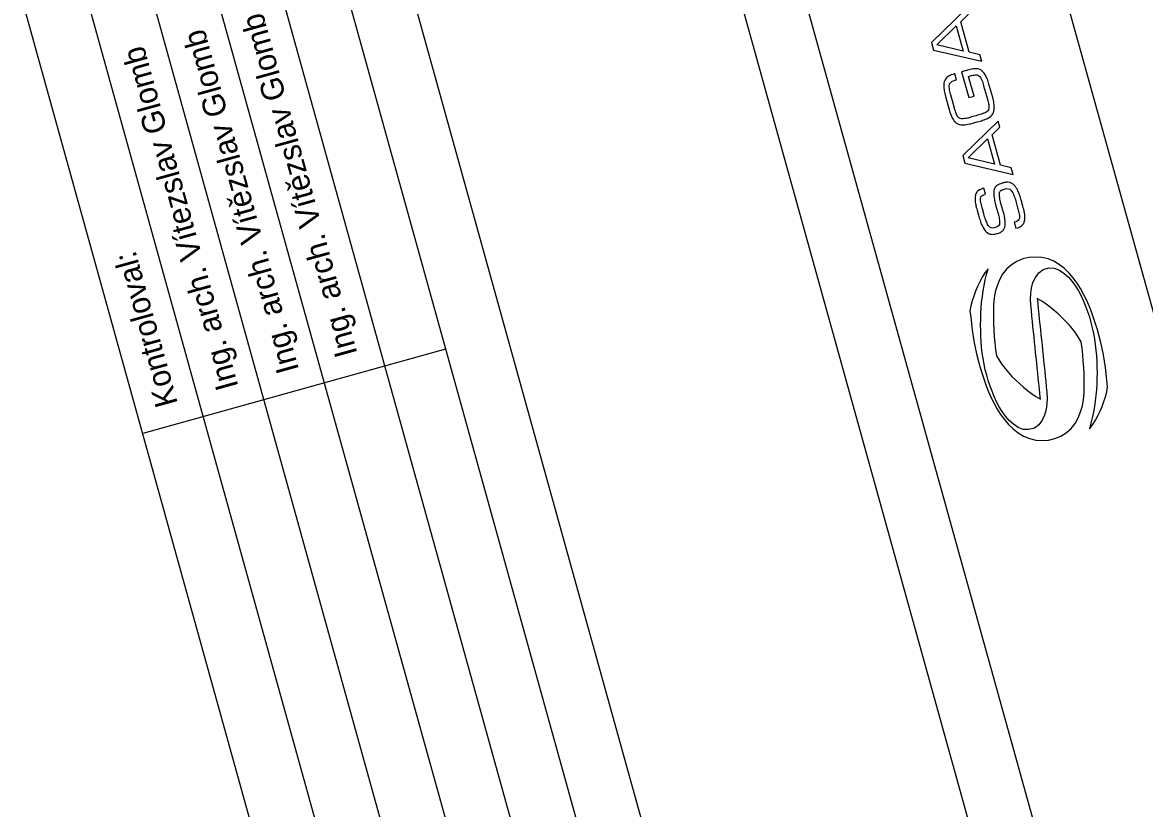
# Model space of a CAD drawing. Extents: x -821122 to -820555, y -1070892 to -1069801.
# Drawn here: x -821033.4 to -820944.2, y -1069943.1 to -1069880.6 of the extents above; entities that cross this region are included whole.
import ezdxf

# ---------------------------------------------------------------- set-up
doc = ezdxf.new("R2010")
doc.units = 0
doc.layers.add('Popisove_pole', color=7, linetype='Continuous')

# ---------------------------------------------------------------- blocks, each defined once
blk = doc.blocks.new('sagasta-logo')
at = {"layer": 'Popisove_pole'}
for p, q in [((-0.4043, 0.0893), (-0.414, 0.0863)), ((-0.3943, 0.0916), (-0.4043, 0.0893)), ((-0.3843, 0.0934), (-0.3943, 0.0916)), ((-0.3742, 0.0949), (-0.3843, 0.0934)), ((-0.3838, 0.0884), (-0.3749, 0.0895)), ((-0.3749, 0.0895), (-0.3659, 0.0903)), ((-0.3641, 0.096), (-0.3742, 0.0949)), ((-0.3659, 0.0903), (-0.3569, 0.0907)), ((-0.3539, 0.0968), (-0.3641, 0.096)), ((-0.3569, 0.0907), (-0.3479, 0.0908)), ((-0.3437, 0.0972), (-0.3539, 0.0968)), ((-0.3479, 0.0908), (-0.3389, 0.0906)), ((-0.3335, 0.0975), (-0.3437, 0.0972)), ((-0.3389, 0.0906), (-0.33, 0.0901)), ((-0.3233, 0.0976), (-0.3335, 0.0975)), ((-0.33, 0.0901), (-0.321, 0.0892)), ((-0.3131, 0.0975), (-0.3233, 0.0976)), ((-0.303, 0.097), (-0.3131, 0.0975)), ((-0.2928, 0.0962), (-0.303, 0.097)), ((-0.2827, 0.0951), (-0.2928, 0.0962)), ((-0.2726, 0.0938), (-0.2827, 0.0951)), ((-0.2625, 0.0922), (-0.2726, 0.0938)), ((-0.2524, 0.0907), (-0.2625, 0.0922)), ((-0.2423, 0.0891), (-0.2524, 0.0907)), ((-0.4415, 0.0731), (-0.4497, 0.067)), ((-0.4328, 0.0783), (-0.4415, 0.0731)), ((-0.4343, 0.0708), (-0.4267, 0.0757)), ((-0.4235, 0.0826), (-0.4328, 0.0783)), ((-0.4267, 0.0757), (-0.4186, 0.0794)), ((-0.414, 0.0863), (-0.4235, 0.0826)), ((-0.4186, 0.0794), (-0.4101, 0.0825)), ((-0.4101, 0.0825), (-0.4015, 0.085)), ((-0.4015, 0.085), (-0.3927, 0.0869)), ((-0.3927, 0.0869), (-0.3838, 0.0884)), ((-0.321, 0.0892), (-0.3121, 0.0881)), ((-0.3121, 0.0881), (-0.3032, 0.0867)), ((-0.3032, 0.0867), (-0.2944, 0.085)), ((-0.2944, 0.085), (-0.2855, 0.0832)), ((-0.2855, 0.0832), (-0.2768, 0.081)), ((-0.2768, 0.081), (-0.2681, 0.0787)), ((-0.2681, 0.0787), (-0.2595, 0.0762)), ((-0.2595, 0.0762), (-0.2509, 0.0735)), ((-0.2509, 0.0735), (-0.2424, 0.0706)), ((-0.235, 0.0855), (-0.2423, 0.0891)), ((-0.228, 0.0814), (-0.235, 0.0855)), ((-0.2211, 0.077), (-0.228, 0.0814)), ((-0.2145, 0.0722), (-0.2211, 0.077)), ((-0.2081, 0.0671), (-0.2145, 0.0722)), ((-0.4572, 0.0602), (-0.4634, 0.0521)), ((-0.4497, 0.067), (-0.4572, 0.0602)), ((-0.4493, 0.0493), (-0.4465, 0.0578)), ((-0.4465, 0.0578), (-0.4412, 0.065)), ((-0.4412, 0.065), (-0.4343, 0.0708)), ((-0.3532, 0.0564), (-0.3606, 0.0526)), ((-0.3457, 0.0599), (-0.3532, 0.0564)), ((-0.338, 0.0629), (-0.3457, 0.0599)), ((-0.3302, 0.0655), (-0.338, 0.0629)), ((-0.3222, 0.0677), (-0.3302, 0.0655)), ((-0.3121, 0.0662), (-0.3222, 0.0677)), ((-0.302, 0.0646), (-0.3121, 0.0662)), ((-0.292, 0.0627), (-0.302, 0.0646)), ((-0.282, 0.0606), (-0.292, 0.0627)), ((-0.2721, 0.0584), (-0.282, 0.0606)), ((-0.2622, 0.0559), (-0.2721, 0.0584)), ((-0.2523, 0.0533), (-0.2622, 0.0559)), ((-0.2424, 0.0706), (-0.2339, 0.0675)), ((-0.2339, 0.0675), (-0.2257, 0.0639)), ((-0.2257, 0.0639), (-0.2174, 0.0604)), ((-0.2174, 0.0604), (-0.2093, 0.0565)), ((-0.2093, 0.0565), (-0.2013, 0.0524)), ((-0.2019, 0.0617), (-0.2081, 0.0671)), ((-0.1961, 0.056), (-0.2019, 0.0617)), ((-0.1906, 0.05), (-0.1961, 0.056)), ((-0.4684, 0.0432), (-0.4717, 0.0335)), ((-0.4634, 0.0521), (-0.4684, 0.0432)), ((-0.4493, 0.0403), (-0.4493, 0.0493)), ((-0.446, 0.0319), (-0.4493, 0.0403)), ((-0.3817, 0.0396), (-0.3885, 0.0348)), ((-0.3748, 0.0442), (-0.3817, 0.0396)), ((-0.3678, 0.0485), (-0.3748, 0.0442)), ((-0.3606, 0.0526), (-0.3678, 0.0485)), ((-0.2426, 0.0503), (-0.2523, 0.0533)), ((-0.2331, 0.0466), (-0.2426, 0.0503)), ((-0.2239, 0.0422), (-0.2331, 0.0466)), ((-0.2152, 0.0369), (-0.2239, 0.0422)), ((-0.2072, 0.0306), (-0.2152, 0.0369)), ((-0.2013, 0.0524), (-0.1935, 0.048)), ((-0.1935, 0.048), (-0.1857, 0.0434)), ((-0.1857, 0.0434), (-0.1906, 0.05)), ((-0.4736, 0.0235), (-0.4741, 0.0133)), ((-0.4717, 0.0335), (-0.4736, 0.0235)), ((-0.4404, 0.0248), (-0.446, 0.0319)), ((-0.4336, 0.019), (-0.4404, 0.0248)), ((-0.4258, 0.0144), (-0.4336, 0.019)), ((-0.4014, 0.0244), (-0.4073, 0.0186)), ((-0.4073, 0.0186), (-0.3991, 0.0172)), ((-0.3951, 0.0298), (-0.4014, 0.0244)), ((-0.3885, 0.0348), (-0.3951, 0.0298)), ((-0.1999, 0.0234), (-0.2072, 0.0306)), ((-0.1939, 0.0152), (-0.1999, 0.0234)), ((-0.4741, 0.0133), (-0.4727, 0.0032)), ((-0.4727, 0.0032), (-0.4699, -0.0066)), ((-0.4176, 0.0108), (-0.4258, 0.0144)), ((-0.409, 0.0082), (-0.4176, 0.0108)), ((-0.4002, 0.0063), (-0.409, 0.0082)), ((-0.3913, 0.0046), (-0.4002, 0.0063)), ((-0.3991, 0.0172), (-0.391, 0.0158)), ((-0.3825, 0.003), (-0.3913, 0.0046)), ((-0.391, 0.0158), (-0.3828, 0.0144)), ((-0.3828, 0.0144), (-0.3747, 0.0131)), ((-0.3743, 0.0016), (-0.3825, 0.003)), ((-0.3747, 0.0131), (-0.3665, 0.0117)), ((-0.3662, 0.0002), (-0.3743, 0.0016)), ((-0.3665, 0.0117), (-0.3584, 0.0103)), ((-0.358, -0.0012), (-0.3662, 0.0002)), ((-0.3584, 0.0103), (-0.3502, 0.0089)), ((-0.3502, 0.0089), (-0.3421, 0.0075)), ((-0.3421, 0.0075), (-0.3339, 0.0062)), ((-0.3339, 0.0062), (-0.3257, 0.0048)), ((-0.3257, 0.0048), (-0.3176, 0.0034)), ((-0.3176, 0.0034), (-0.3094, 0.002)), ((-0.3094, 0.002), (-0.3013, 0.0006)), ((-0.3013, 0.0006), (-0.2931, -0.0007)), ((-0.1894, 0.0061), (-0.1939, 0.0152)), ((-0.1866, -0.0037), (-0.1894, 0.0061)), ((-0.4699, -0.0066), (-0.4654, -0.0157)), ((-0.4654, -0.0157), (-0.4594, -0.024)), ((-0.3499, -0.0025), (-0.358, -0.0012)), ((-0.3417, -0.0039), (-0.3499, -0.0025)), ((-0.3336, -0.0053), (-0.3417, -0.0039)), ((-0.3254, -0.0067), (-0.3336, -0.0053)), ((-0.3173, -0.0081), (-0.3254, -0.0067)), ((-0.3091, -0.0094), (-0.3173, -0.0081)), ((-0.301, -0.0108), (-0.3091, -0.0094)), ((-0.2928, -0.0122), (-0.301, -0.0108)), ((-0.2931, -0.0007), (-0.285, -0.0021)), ((-0.2846, -0.0136), (-0.2928, -0.0122)), ((-0.285, -0.0021), (-0.2768, -0.0035)), ((-0.2765, -0.015), (-0.2846, -0.0136)), ((-0.2768, -0.0035), (-0.268, -0.0051)), ((-0.2683, -0.0163), (-0.2765, -0.015)), ((-0.2602, -0.0177), (-0.2683, -0.0163)), ((-0.268, -0.0051), (-0.2591, -0.0068)), ((-0.252, -0.0191), (-0.2602, -0.0177)), ((-0.2591, -0.0068), (-0.2504, -0.0087)), ((-0.2504, -0.0087), (-0.2417, -0.0114)), ((-0.2417, -0.0114), (-0.2335, -0.0149)), ((-0.2335, -0.0149), (-0.2258, -0.0195)), ((-0.1852, -0.0139), (-0.1866, -0.0037)), ((-0.1857, -0.024), (-0.1852, -0.0139)), ((-0.4594, -0.024), (-0.4521, -0.0311)), ((-0.4521, -0.0311), (-0.4441, -0.0374)), ((-0.2776, -0.0401), (-0.2708, -0.0354)), ((-0.2708, -0.0354), (-0.2642, -0.0304)), ((-0.2642, -0.0304), (-0.258, -0.025)), ((-0.258, -0.025), (-0.252, -0.0191)), ((-0.2258, -0.0195), (-0.2189, -0.0253)), ((-0.2189, -0.0253), (-0.2134, -0.0324)), ((-0.2134, -0.0324), (-0.21, -0.0408)), ((-0.1909, -0.0437), (-0.1876, -0.034)), ((-0.1876, -0.034), (-0.1857, -0.024)), ((-0.4659, -0.0485), (-0.4736, -0.0439)), ((-0.4736, -0.0439), (-0.4687, -0.0505)), ((-0.4687, -0.0505), (-0.4632, -0.0565)), ((-0.458, -0.0529), (-0.4659, -0.0485)), ((-0.45, -0.057), (-0.458, -0.0529)), ((-0.4441, -0.0374), (-0.4354, -0.0428)), ((-0.4354, -0.0428), (-0.4262, -0.0471)), ((-0.4262, -0.0471), (-0.4167, -0.0508)), ((-0.4167, -0.0508), (-0.407, -0.0538)), ((-0.3061, -0.0569), (-0.2987, -0.0531)), ((-0.2987, -0.0531), (-0.2915, -0.049)), ((-0.2915, -0.049), (-0.2845, -0.0447)), ((-0.2845, -0.0447), (-0.2776, -0.0401)), ((-0.21, -0.0498), (-0.2128, -0.0583)), ((-0.21, -0.0408), (-0.21, -0.0498)), ((-0.2021, -0.0607), (-0.1959, -0.0526)), ((-0.1959, -0.0526), (-0.1909, -0.0437)), ((-0.4632, -0.0565), (-0.4574, -0.0622)), ((-0.4574, -0.0622), (-0.4512, -0.0676)), ((-0.4512, -0.0676), (-0.4449, -0.0727)), ((-0.4419, -0.0609), (-0.45, -0.057)), ((-0.4336, -0.0644), (-0.4419, -0.0609)), ((-0.4254, -0.068), (-0.4336, -0.0644)), ((-0.4169, -0.0711), (-0.4254, -0.068)), ((-0.4084, -0.074), (-0.4169, -0.0711)), ((-0.407, -0.0538), (-0.3971, -0.0564)), ((-0.3971, -0.0564), (-0.3872, -0.0589)), ((-0.3872, -0.0589), (-0.3773, -0.0611)), ((-0.3773, -0.0611), (-0.3673, -0.0632)), ((-0.3673, -0.0632), (-0.3573, -0.0651)), ((-0.3573, -0.0651), (-0.3472, -0.0667)), ((-0.3472, -0.0667), (-0.3371, -0.0682)), ((-0.3371, -0.0682), (-0.3291, -0.0661)), ((-0.3291, -0.0661), (-0.3213, -0.0635)), ((-0.3213, -0.0635), (-0.3136, -0.0604)), ((-0.3136, -0.0604), (-0.3061, -0.0569)), ((-0.225, -0.0713), (-0.2326, -0.0762)), ((-0.2181, -0.0655), (-0.225, -0.0713)), ((-0.2128, -0.0583), (-0.2181, -0.0655)), ((-0.2178, -0.0736), (-0.2096, -0.0675)), ((-0.2096, -0.0675), (-0.2021, -0.0607)), ((-0.4449, -0.0727), (-0.4382, -0.0775)), ((-0.4382, -0.0775), (-0.4314, -0.0819)), ((-0.4314, -0.0819), (-0.4243, -0.0861)), ((-0.4243, -0.0861), (-0.417, -0.0896)), ((-0.3998, -0.0767), (-0.4084, -0.074)), ((-0.3912, -0.0792), (-0.3998, -0.0767)), ((-0.3825, -0.0815), (-0.3912, -0.0792)), ((-0.3738, -0.0837), (-0.3825, -0.0815)), ((-0.365, -0.0855), (-0.3738, -0.0837)), ((-0.3561, -0.0872), (-0.365, -0.0855)), ((-0.3472, -0.0886), (-0.3561, -0.0872)), ((-0.3383, -0.0897), (-0.3472, -0.0886)), ((-0.2755, -0.0889), (-0.2844, -0.09)), ((-0.2666, -0.0874), (-0.2755, -0.0889)), ((-0.2579, -0.0855), (-0.2666, -0.0874)), ((-0.2492, -0.083), (-0.2579, -0.0855)), ((-0.2551, -0.0898), (-0.2453, -0.0868)), ((-0.2407, -0.08), (-0.2492, -0.083)), ((-0.2453, -0.0868), (-0.2358, -0.0831)), ((-0.2326, -0.0762), (-0.2407, -0.08)), ((-0.2358, -0.0831), (-0.2266, -0.0788)), ((-0.2266, -0.0788), (-0.2178, -0.0736)), ((-0.417, -0.0896), (-0.4069, -0.0912)), ((-0.4069, -0.0912), (-0.3968, -0.0928)), ((-0.3968, -0.0928), (-0.3868, -0.0943)), ((-0.3868, -0.0943), (-0.3766, -0.0956)), ((-0.3766, -0.0956), (-0.3665, -0.0967)), ((-0.3665, -0.0967), (-0.3564, -0.0976)), ((-0.3564, -0.0976), (-0.3462, -0.098)), ((-0.3462, -0.098), (-0.336, -0.0982)), ((-0.3294, -0.0906), (-0.3383, -0.0897)), ((-0.336, -0.0982), (-0.3258, -0.0981)), ((-0.3204, -0.0911), (-0.3294, -0.0906)), ((-0.3258, -0.0981), (-0.3156, -0.0978)), ((-0.3114, -0.0913), (-0.3204, -0.0911)), ((-0.3156, -0.0978), (-0.3054, -0.0973)), ((-0.3024, -0.0912), (-0.3114, -0.0913)), ((-0.3054, -0.0973), (-0.2952, -0.0966)), ((-0.2934, -0.0908), (-0.3024, -0.0912)), ((-0.2952, -0.0966), (-0.2851, -0.0955)), ((-0.2844, -0.09), (-0.2934, -0.0908)), ((-0.2851, -0.0955), (-0.275, -0.094)), ((-0.275, -0.094), (-0.265, -0.0922)), ((-0.265, -0.0922), (-0.2551, -0.0898))]:
    blk.add_line(p, q, dxfattribs=at)
for points in [[(-0.0604, -0.0144), (-0.0605, -0.0121), (-0.0607, -0.0098), (-0.0608, -0.009), (-0.0613, -0.0068), (-0.0622, -0.0048), (-0.0625, -0.0042), (-0.0637, -0.0023), (-0.0654, -0.0007), (-0.0667, 0.0003), (-0.0686, 0.0013), (-0.0709, 0.0023), (-0.0724, 0.0027), (-0.0745, 0.0032), (-0.0767, 0.0037), (-0.0792, 0.004), (-0.0796, 0.004), (-0.0816, 0.0042), (-0.0837, 0.0044), (-0.0859, 0.0045), (-0.0883, 0.0046), (-0.0908, 0.0046), (-0.102, 0.0046), (-0.1025, 0.0046), (-0.1051, 0.0046), (-0.1074, 0.0046), (-0.1095, 0.0047), (-0.1114, 0.0048), (-0.1136, 0.005), (-0.1158, 0.0052), (-0.1178, 0.0056), (-0.1201, 0.0062), (-0.1224, 0.0072), (-0.1244, 0.0091), (-0.1253, 0.0115), (-0.1254, 0.0129), (-0.1255, 0.0152), (-0.1255, 0.0165), (-0.1251, 0.0188), (-0.1243, 0.0211), (-0.1226, 0.0229), (-0.1205, 0.0241), (-0.1193, 0.0246), (-0.1174, 0.0252), (-0.1151, 0.0256), (-0.1125, 0.026), (-0.1108, 0.0262), (-0.1088, 0.0263), (-0.1067, 0.0264), (-0.1043, 0.0265), (-0.1019, 0.0266), (-0.0993, 0.0266), (-0.0911, 0.0266), (-0.0897, 0.0266), (-0.0872, 0.0266), (-0.0849, 0.0265), (-0.0829, 0.0264), (-0.081, 0.0263), (-0.0785, 0.026), (-0.0763, 0.0256), (-0.0745, 0.025), (-0.0725, 0.0237), (-0.0713, 0.022), (-0.0707, 0.0204), (-0.0704, 0.0182), (-0.0703, 0.0154), (-0.0604, 0.0154), (-0.0604, 0.0179), (-0.0606, 0.0202), (-0.0609, 0.0222), (-0.061, 0.023), (-0.0618, 0.0252), (-0.0628, 0.0271), (-0.0633, 0.0278), (-0.0647, 0.0294), (-0.0665, 0.0309), (-0.068, 0.0317), (-0.07, 0.0326), (-0.0722, 0.0334), (-0.0736, 0.0338), (-0.0757, 0.0342), (-0.0779, 0.0346), (-0.0803, 0.0349), (-0.082, 0.035), (-0.0842, 0.0352), (-0.0864, 0.0353), (-0.0887, 0.0353), (-0.0911, 0.0354), (-0.0993, 0.0354), (-0.1014, 0.0354), (-0.1038, 0.0353), (-0.1061, 0.0352), (-0.1083, 0.0351), (-0.1103, 0.035), (-0.1123, 0.0348), (-0.1134, 0.0347), (-0.1158, 0.0344), (-0.118, 0.034), (-0.1201, 0.0336), (-0.122, 0.033), (-0.1226, 0.0329), (-0.1249, 0.0321), (-0.1269, 0.0312), (-0.1286, 0.0302), (-0.1298, 0.0294), (-0.1314, 0.0278), (-0.1328, 0.0262), (-0.1333, 0.0254), (-0.1342, 0.0234), (-0.1349, 0.0212), (-0.1351, 0.0199), (-0.1354, 0.0176), (-0.1354, 0.0152), (-0.1354, 0.0141), (-0.1353, 0.0118), (-0.1351, 0.0096), (-0.135, 0.009), (-0.1344, 0.0068), (-0.1335, 0.0048), (-0.1331, 0.0041), (-0.1318, 0.0024), (-0.13, 0.0008), (-0.1283, -0.0002), (-0.1263, -0.0012), (-0.124, -0.002), (-0.1237, -0.0021), (-0.1218, -0.0026), (-0.1197, -0.003), (-0.1174, -0.0033), (-0.1149, -0.0036), (-0.1134, -0.0038), (-0.1114, -0.004), (-0.1092, -0.0041), (-0.1069, -0.0042), (-0.1045, -0.0042), (-0.102, -0.0042), (-0.0908, -0.0042), (-0.0885, -0.0042), (-0.0861, -0.0043), (-0.0838, -0.0044), (-0.0818, -0.0046), (-0.08, -0.0048), (-0.0776, -0.0053), (-0.0754, -0.0059), (-0.0737, -0.0067), (-0.072, -0.0082), (-0.0709, -0.0101), (-0.0707, -0.011), (-0.0704, -0.0131), (-0.0703, -0.0156), (-0.0703, -0.017), (-0.0706, -0.0193), (-0.0715, -0.0217), (-0.073, -0.0236), (-0.0749, -0.025), (-0.0756, -0.0253), (-0.0775, -0.026), (-0.0797, -0.0266), (-0.0822, -0.0271), (-0.0826, -0.0272), (-0.0845, -0.0274), (-0.0866, -0.0276), (-0.0888, -0.0277), (-0.0912, -0.0278), (-0.0938, -0.0278), (-0.1047, -0.0278), (-0.1063, -0.0278), (-0.1088, -0.0278), (-0.111, -0.0277), (-0.1131, -0.0276), (-0.1149, -0.0275), (-0.1172, -0.0273), (-0.1194, -0.0268), (-0.1213, -0.0262), (-0.1232, -0.0249), (-0.1245, -0.0231), (-0.125, -0.0215), (-0.1254, -0.0193), (-0.1255, -0.0165), (-0.1354, -0.0165), (-0.1353, -0.0191), (-0.1352, -0.0214), (-0.1349, -0.0233), (-0.1347, -0.0241), (-0.134, -0.0263), (-0.1329, -0.0282), (-0.1325, -0.0288), (-0.1311, -0.0305), (-0.1293, -0.032), (-0.1279, -0.0329), (-0.1258, -0.0338), (-0.1236, -0.0346), (-0.1223, -0.035), (-0.1202, -0.0354), (-0.1179, -0.0358), (-0.1155, -0.0361), (-0.1138, -0.0362), (-0.1118, -0.0364), (-0.1095, -0.0365), (-0.1072, -0.0365), (-0.1047, -0.0366), (-0.0938, -0.0366), (-0.0928, -0.0366), (-0.0904, -0.0365), (-0.0881, -0.0364), (-0.0858, -0.0363), (-0.0838, -0.0362), (-0.0818, -0.036), (-0.0792, -0.0355), (-0.077, -0.0351), (-0.0749, -0.0346), (-0.0727, -0.0339), (-0.0705, -0.0331), (-0.0685, -0.0321), (-0.0668, -0.0309), (-0.0658, -0.0301), (-0.0642, -0.0285), (-0.0629, -0.0268), (-0.0624, -0.0259), (-0.0615, -0.0238), (-0.0609, -0.0216), (-0.0607, -0.0202), (-0.0604, -0.018), (-0.0604, -0.0156), (-0.0604, -0.0144)], [(-0.0012, 0.0339), (-0.0139, 0.0339), (-0.0515, -0.0351), (-0.0406, -0.0351), (-0.0322, -0.0197), (0.0179, -0.0197), (0.0263, -0.0351), (0.0363, -0.0351), (-0.0012, 0.0339)], [(-0.0071, 0.0266), (0.0136, -0.0109), (-0.0279, -0.0109), (-0.0071, 0.0266)], [(0.0556, 0.0205), (0.0565, 0.0223), (0.0579, 0.0238), (0.0599, 0.0249), (0.0612, 0.0254), (0.0633, 0.0259), (0.0658, 0.0262), (0.0659, 0.0262), (0.0678, 0.0263), (0.07, 0.0264), (0.0723, 0.0265), (0.0748, 0.0265), (0.0967, 0.0265), (0.0981, 0.0265), (0.1005, 0.0264), (0.1028, 0.0263), (0.1049, 0.0262), (0.1067, 0.026), (0.1069, 0.026), (0.1093, 0.0256), (0.1114, 0.025), (0.1132, 0.0242), (0.114, 0.0236), (0.1155, 0.022), (0.1165, 0.0199), (0.1169, 0.0184), (0.1173, 0.0164), (0.1175, 0.0139), (0.1175, 0.0111), (0.1274, 0.0111), (0.1274, 0.0125), (0.1274, 0.0149), (0.1272, 0.0172), (0.1269, 0.0191), (0.1266, 0.0208), (0.1259, 0.023), (0.125, 0.025), (0.1243, 0.0263), (0.123, 0.028), (0.1214, 0.0296), (0.1197, 0.0308), (0.1178, 0.0319), (0.1156, 0.0328), (0.1142, 0.0333), (0.1121, 0.0338), (0.1099, 0.0343), (0.1075, 0.0346), (0.1058, 0.0349), (0.1036, 0.035), (0.1014, 0.0352), (0.0991, 0.0353), (0.0967, 0.0353), (0.0748, 0.0353), (0.0729, 0.0353), (0.0704, 0.0352), (0.0681, 0.0351), (0.066, 0.0349), (0.0639, 0.0346), (0.0621, 0.0343), (0.0617, 0.0343), (0.0593, 0.0337), (0.0572, 0.033), (0.0552, 0.0323), (0.0534, 0.0313), (0.0527, 0.0309), (0.0508, 0.0296), (0.0493, 0.028), (0.048, 0.0263), (0.0476, 0.0257), (0.0466, 0.0237), (0.0458, 0.0216), (0.0453, 0.0192), (0.0449, 0.0173), (0.0446, 0.0151), (0.0444, 0.0128), (0.0443, 0.0103), (0.0442, 0.0087), (0.0442, 0.0065), (0.0441, 0.0042), (0.0441, 0.0019), (0.0441, -0.0006), (0.0441, -0.0025), (0.0441, -0.0049), (0.0442, -0.0072), (0.0442, -0.0094), (0.0443, -0.0115), (0.0444, -0.0139), (0.0446, -0.0162), (0.0449, -0.0184), (0.0453, -0.0205), (0.0454, -0.0213), (0.0461, -0.0235), (0.0469, -0.0256), (0.048, -0.0275), (0.0484, -0.0282), (0.0498, -0.0298), (0.0514, -0.0313), (0.0537, -0.0328), (0.0554, -0.0336), (0.0574, -0.0344), (0.0596, -0.035), (0.062, -0.0355), (0.0635, -0.0358), (0.0655, -0.036), (0.0676, -0.0362), (0.0699, -0.0364), (0.0723, -0.0365), (0.0748, -0.0365), (0.0967, -0.0365), (0.0989, -0.0365), (0.1013, -0.0364), (0.1035, -0.0363), (0.1056, -0.0361), (0.1076, -0.0359), (0.1093, -0.0356), (0.1116, -0.0352), (0.1137, -0.0346), (0.1156, -0.034), (0.1178, -0.033), (0.1197, -0.0319), (0.1214, -0.0306), (0.1225, -0.0295), (0.1239, -0.0278), (0.125, -0.0258), (0.1258, -0.024), (0.1265, -0.0219), (0.1269, -0.0195), (0.127, -0.0187), (0.1273, -0.0166), (0.1274, -0.0142), (0.1274, -0.0118), (0.1274, 0.0003), (0.0849, 0.0003), (0.0849, -0.0085), (0.1175, -0.0085), (0.1175, -0.0118), (0.1175, -0.0133), (0.1174, -0.0157), (0.1172, -0.0178), (0.1169, -0.02), (0.1162, -0.022), (0.1156, -0.0231), (0.1141, -0.0248), (0.1127, -0.0257), (0.1105, -0.0265), (0.1094, -0.0268), (0.1073, -0.0272), (0.1049, -0.0274), (0.1036, -0.0275), (0.1015, -0.0276), (0.0992, -0.0277), (0.0967, -0.0277), (0.0748, -0.0277), (0.0746, -0.0277), (0.072, -0.0277), (0.0697, -0.0276), (0.0676, -0.0275), (0.0657, -0.0274), (0.0641, -0.0272), (0.0618, -0.0267), (0.06, -0.0261), (0.058, -0.025), (0.0564, -0.0234), (0.0554, -0.0212), (0.0548, -0.0187), (0.0545, -0.0165), (0.0542, -0.0142), (0.0541, -0.0117), (0.0541, -0.0102), (0.0541, -0.0081), (0.0541, -0.0058), (0.054, -0.0033), (0.054, -0.0006), (0.054, 0.0018), (0.0541, 0.0043), (0.0541, 0.0066), (0.0541, 0.0087), (0.0541, 0.0105), (0.0541, 0.0108), (0.0542, 0.0133), (0.0545, 0.0156), (0.0548, 0.0179), (0.0556, 0.0205)], [(0.1854, 0.0339), (0.1727, 0.0339), (0.1351, -0.0351), (0.1459, -0.0351), (0.1544, -0.0197), (0.2044, -0.0197), (0.2129, -0.0351), (0.2229, -0.0351), (0.1854, 0.0339)], [(0.1795, 0.0266), (0.2002, -0.0109), (0.1586, -0.0109), (0.1795, 0.0266)]]:
    blk.add_lwpolyline(points, dxfattribs=at)

msp = doc.modelspace()

# ---------------------------------------------------------------- linework, layer by layer
at = {"layer": 'Popisove_pole'}
for p, q in [((-820910.77, -1070021.294), (-820956.283, -1069857.5)), ((-820968.58, -1070037.358), (-821014.093, -1069873.564)), ((-820973.397, -1070038.696), (-821018.911, -1069874.902)), ((-820978.215, -1070040.035), (-821023.728, -1069876.241)), ((-820983.032, -1070041.374), (-821028.545, -1069877.579)), ((-820999.718, -1069906.622), (-821023.805, -1069913.315))]:
    msp.add_line(p, q, dxfattribs=at)
for points in [[(-820930.04, -1070026.649), (-820975.553, -1069862.855), (-820927.378, -1069849.468), (-820881.865, -1070013.263)], [(-820958.945, -1070034.681), (-821004.458, -1069870.886), (-820980.371, -1069864.193), (-820934.858, -1070027.987)], [(-820987.85, -1070042.712), (-821033.363, -1069878.918), (-821009.276, -1069872.225), (-820963.762, -1070036.019)]]:
    msp.add_lwpolyline(points, close=True, dxfattribs=at)

# ---------------------------------------------------------------- block references
at = {"layer": 'Popisove_pole', "xscale": 49.999999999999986, "yscale": 49.999999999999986, "rotation": 105.52891348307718}
msp.add_blockref('sagasta-logo', (-820956.988, -1069890.702), dxfattribs=at)

# ---------------------------------------------------------------- texts
at = {"layer": 'Popisove_pole'}
for s, p in [('Ing. arch. Vítězslav Glomb', (-821006.721, -1069906.963)), ('Ing. arch. Vítězslav Glomb', (-821011.36, -1069908.252)), ('Ing. arch. Vítezslav Glomb', (-821016.177, -1069909.59)), ('Kontroloval:', (-821020.995, -1069910.929))]:
    msp.add_text(s, height=1.8, rotation=105.52891, dxfattribs=at).set_placement(p)

doc.saveas('drawing.dxf')
